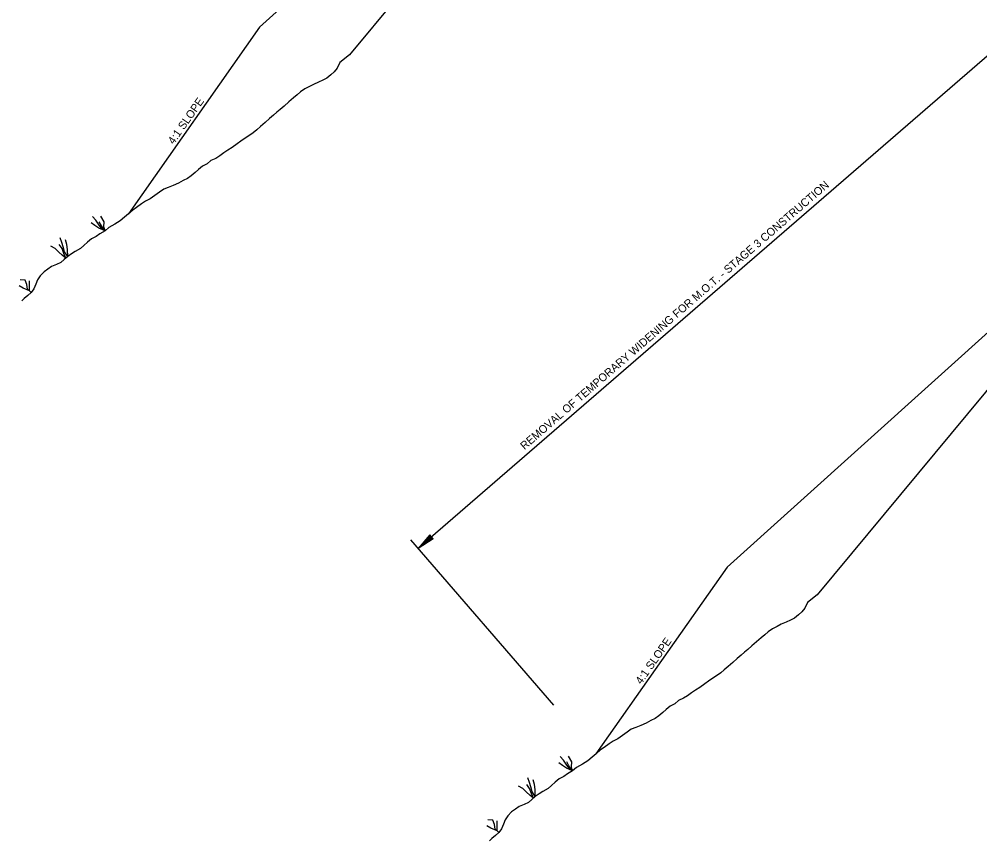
# Model space of a CAD drawing. Extents: x 192699 to 285914, y 194342 to 233219.
# Drawn here: x 262821.96 to 262865.17, y 213540.87 to 213577.84 of the extents above; entities that cross this region are included whole.
import ezdxf

# ---------------------------------------------------------------- set-up
doc = ezdxf.new("R2010")
doc.units = 0
doc.layers.add('R_Draft', color=7, linetype='Continuous')
doc.layers.add('TYPICAL SECTION FOR MOT', color=7, linetype='Continuous')

msp = doc.modelspace()

# ---------------------------------------------------------------- linework, layer by layer
at = {"layer": 'R_Draft'}
for p, q in [((262840.431, 213554.64), (262839.905, 213554.026)), ((262840.588, 213554.459), (262839.905, 213554.026)), ((262840.444, 213554.625), (262840.006, 213554.114)), ((262840.575, 213554.474), (262840.006, 213554.114)), ((262840.457, 213554.61), (262840.11, 213554.204)), ((262840.562, 213554.49), (262840.11, 213554.204)), ((262840.47, 213554.595), (262840.21, 213554.291)), ((262840.548, 213554.505), (262840.21, 213554.291)), ((262840.484, 213554.579), (262840.313, 213554.38)), ((262840.535, 213554.52), (262840.313, 213554.38)), ((262840.497, 213554.564), (262840.414, 213554.467)), ((262840.522, 213554.535), (262840.414, 213554.467)), ((262840.588, 213554.459), (262840.431, 213554.64))]:
    msp.add_line(p, q, dxfattribs=at)
at = {"layer": 'TYPICAL SECTION FOR MOT'}
for p, q in [((262852.272, 213595.062), (262832.769, 213577.484)), ((262852.351, 213594.972), (262836.824, 213576.239)), ((262867.28, 213577.726), (262839.905, 213554.026)), ((262832.769, 213577.484), (262826.869, 213569.083)), ((262873.309, 213570.762), (262853.807, 213553.184)), ((262873.388, 213570.671), (262857.861, 213551.938)), ((262846.012, 213546.971), (262839.577, 213554.404)), ((262853.807, 213553.184), (262847.907, 213544.783))]:
    msp.add_line(p, q, dxfattribs=at)
for points in [[(262836.824, 213576.239), (262836.38, 213575.895), (262836.27, 213575.631), (262836.132, 213575.478), (262835.978, 213575.344), (262835.803, 213575.193), (262835.615, 213575.097), (262835.427, 213575.002), (262835.202, 213574.909), (262835.014, 213574.814), (262834.807, 213574.702), (262834.616, 213574.571), (262834.461, 213574.437), (262834.306, 213574.303), (262834.093, 213574.118), (262833.88, 213573.934), (262833.706, 213573.783), (262833.552, 213573.65), (262833.397, 213573.516), (262833.223, 213573.365), (262833.029, 213573.197), (262832.816, 213573.013), (262832.642, 213572.862), (262832.487, 213572.728), (262832.297, 213572.597), (262832.125, 213572.482), (262831.934, 213572.351), (262831.763, 213572.236), (262831.533, 213572.071), (262831.342, 213571.94), (262831.171, 213571.825), (262830.98, 213571.694), (262830.808, 213571.579), (262830.584, 213571.486), (262830.41, 213571.336), (262830.202, 213571.224), (262830.028, 213571.073), (262829.873, 213570.939), (262829.699, 213570.788), (262829.528, 213570.674), (262829.339, 213570.578), (262829.132, 213570.466), (262828.888, 213570.357), (262828.664, 213570.264), (262828.459, 213570.188), (262828.268, 213570.057), (262828.057, 213569.909), (262827.847, 213569.76), (262827.64, 213569.648), (262827.468, 213569.534), (262827.238, 213569.369), (262827.067, 213569.254), (262826.873, 213569.087), (262826.699, 213568.936), (262826.506, 213568.768), (262826.26, 213568.623), (262825.994, 213568.461), (262825.82, 213568.31), (262825.593, 213568.181), (262825.421, 213568.066), (262825.214, 213567.954), (262825.039, 213567.804), (262824.865, 213567.653), (262824.711, 213567.519), (262824.484, 213567.39), (262824.312, 213567.275), (262824.141, 213567.161), (262823.986, 213567.027), (262823.831, 213566.893), (262823.643, 213566.797), (262823.418, 213566.705), (262823.247, 213566.59), (262823.075, 213566.475), (262822.898, 213566.289), (262822.777, 213566.116), (262822.709, 213565.921), (262822.621, 213565.71), (262822.5, 213565.537), (262822.345, 213565.403), (262822.19, 213565.269), (262822.074, 213565.169)], [(262825.82, 213568.31), (262825.648, 213568.449), (262825.524, 213568.612), (262825.411, 213568.802), (262825.25, 213568.968)], [(262825.82, 213568.31), (262825.77, 213568.504), (262825.786, 213568.72), (262825.632, 213568.976)], [(262825.82, 213568.31), (262825.539, 213568.439), (262825.366, 213568.56), (262825.193, 213568.681)], [(262825.82, 213568.31), (262825.655, 213568.539), (262825.56, 213568.728)], [(262824.063, 213567.094), (262823.969, 213567.3), (262823.885, 213567.515), (262823.762, 213567.696)], [(262824.141, 213567.161), (262823.992, 213567.371), (262823.936, 213567.593), (262823.878, 213567.796), (262823.802, 213568.001)], [(262824.141, 213567.161), (262824.126, 213567.47), (262824.098, 213567.699), (262824.049, 213567.911)], [(262824.063, 213567.094), (262823.89, 213567.215), (262823.747, 213567.361), (262823.577, 213567.519), (262823.376, 213567.633)], [(262822.5, 213565.537), (262822.338, 213565.685), (262822.308, 213565.896), (262822.222, 213566.092), (262821.997, 213566.118)], [(262822.419, 213565.611), (262822.43, 213565.832), (262822.419, 213566.06)], [(262822.419, 213565.611), (262822.142, 213565.735), (262821.96, 213565.848)], [(262857.861, 213551.938), (262857.418, 213551.594), (262857.308, 213551.33), (262857.17, 213551.177), (262857.015, 213551.043), (262856.841, 213550.892), (262856.653, 213550.797), (262856.464, 213550.702), (262856.24, 213550.609), (262856.052, 213550.514), (262855.844, 213550.402), (262855.653, 213550.27), (262855.498, 213550.136), (262855.344, 213550.002), (262855.131, 213549.818), (262854.918, 213549.634), (262854.744, 213549.483), (262854.589, 213549.349), (262854.434, 213549.215), (262854.26, 213549.064), (262854.067, 213548.897), (262853.854, 213548.712), (262853.68, 213548.562), (262853.525, 213548.428), (262853.334, 213548.296), (262853.163, 213548.182), (262852.972, 213548.05), (262852.8, 213547.936), (262852.571, 213547.771), (262852.38, 213547.639), (262852.208, 213547.525), (262852.017, 213547.393), (262851.846, 213547.279), (262851.621, 213547.186), (262851.447, 213547.035), (262851.24, 213546.923), (262851.065, 213546.772), (262850.911, 213546.638), (262850.737, 213546.488), (262850.565, 213546.373), (262850.377, 213546.278), (262850.169, 213546.166), (262849.925, 213546.056), (262849.701, 213545.963), (262849.496, 213545.887), (262849.305, 213545.756), (262849.095, 213545.608), (262848.885, 213545.46), (262848.677, 213545.348), (262848.505, 213545.233), (262848.276, 213545.068), (262848.104, 213544.954), (262847.911, 213544.786), (262847.737, 213544.635), (262847.543, 213544.468), (262847.297, 213544.322), (262847.031, 213544.16), (262846.857, 213544.009), (262846.63, 213543.88), (262846.459, 213543.766), (262846.251, 213543.654), (262846.077, 213543.503), (262845.903, 213543.352), (262845.748, 213543.218), (262845.521, 213543.089), (262845.349, 213542.975), (262845.178, 213542.86), (262845.023, 213542.726), (262844.868, 213542.592), (262844.68, 213542.497), (262844.456, 213542.404), (262844.284, 213542.289), (262844.113, 213542.175), (262843.936, 213541.988), (262843.815, 213541.815), (262843.746, 213541.621), (262843.658, 213541.409), (262843.537, 213541.237), (262843.382, 213541.103), (262843.228, 213540.969), (262843.112, 213540.868)], [(262846.857, 213544.009), (262846.576, 213544.138), (262846.403, 213544.26), (262846.231, 213544.381)], [(262846.857, 213544.009), (262846.686, 213544.149), (262846.561, 213544.312), (262846.448, 213544.501), (262846.288, 213544.667)], [(262846.857, 213544.009), (262846.692, 213544.239), (262846.597, 213544.427)], [(262846.857, 213544.009), (262846.808, 213544.203), (262846.823, 213544.42), (262846.669, 213544.676)], [(262845.178, 213542.86), (262845.03, 213543.07), (262844.973, 213543.292), (262844.915, 213543.496), (262844.839, 213543.701)], [(262845.178, 213542.86), (262845.164, 213543.17), (262845.135, 213543.398), (262845.087, 213543.61)], [(262845.101, 213542.793), (262844.928, 213542.914), (262844.784, 213543.061), (262844.614, 213543.218), (262844.414, 213543.332)], [(262845.101, 213542.793), (262845.007, 213542.999), (262844.922, 213543.214), (262844.799, 213543.395)], [(262843.537, 213541.237), (262843.375, 213541.384), (262843.345, 213541.595), (262843.26, 213541.792), (262843.035, 213541.817)], [(262843.456, 213541.31), (262843.468, 213541.532), (262843.457, 213541.759)], [(262843.456, 213541.31), (262843.18, 213541.435), (262842.997, 213541.548)]]:
    msp.add_lwpolyline(points, dxfattribs=at)

# ---------------------------------------------------------------- texts
for s, rotation, p in [('4:1 SLOPE', 54.9195, (262828.907, 213572.179)), ('REMOVAL OF TEMPORARY WIDENING FOR M.O.T. - STAGE 3 CONSTRUCTION', 40.8833, (262844.692, 213558.441)), ('4:1 SLOPE', 54.9195, (262849.944, 213547.878))]:
    msp.add_text(s, height=0.36, rotation=rotation, dxfattribs=at).set_placement(p)

doc.saveas('drawing.dxf')
